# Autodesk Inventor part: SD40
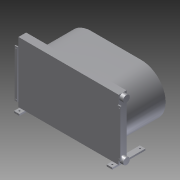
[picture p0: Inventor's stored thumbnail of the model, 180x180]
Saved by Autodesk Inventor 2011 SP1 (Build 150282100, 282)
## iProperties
Created: 2012-10
Part Number: SD40
Document SubType Name: Modeling
Designer: zazhorin
Density: 1 g/cm^3
Author: zazhorin
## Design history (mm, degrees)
sketch "Эскиз1"
  geometry: L1 (0, 0)-(50, 0); L2 (50, 0)-(50, 300); L3 (50, 300)-(0, 300); L4 (0, 300)-(0, 0); L5 (840, 0)-(890, 0); L6 (890, 0)-(890, 300); L7 (890, 300)-(840, 300); L8 (840, 300)-(840, 0); C1 r 7 at (25, 25); C2 r 7 at (25, 275); C3 r 7 at (865, 275); C4 r 7 at (865, 25)
  constraints: 16 end point, 4 centre point, 4 parallel, 2 horizontal, 2 perpendicular
  dimensions: "d0" = 50 distance of L1.start L1.end; "d1" = 300 distance of L3.end L1.start; "d2" = 790 distance between parallel lines of L8 L2; "d3" = 50 distance of L5.start L5.end; "d4" = 300 distance of L5.end L6.end; "d5" = 25 distance from line of C1.centre L1; "d6" = 14 diameter of C1; "d7" = 25 distance from line of C1.centre L4; "d8" = 25 distance from line of L3 C2.centre; "d9" = 14 diameter of C2; "d10" = 25 distance from line of C2.centre L4; "d11" = 300 distance between parallel lines of L5 L3; "d12" = 25 distance from line of C3.centre L8; "d13" = 25 distance from line of C3.centre L7; "d14" = 14 diameter of C3; "d15" = 25 distance from line of C4.centre L8; "d16" = 25 distance from line of C4.centre L5; "d17" = 14 diameter of C4
extrude "Выдавливание1" new body sketch "Эскиз1" distance "d18" = 15; taper "d19" = 0 deg
node "РабПлоскость1"
sketch "Эскиз3"
  geometry: L1 (445, 550)-(924, 550); L2 (445, 275)-(1052.827, 275); L3 (924, 275)-(924, 490); L4 (924, 490)-(899, 490); L5 (899, 490)-(899, 275); L6 (924, 275)-(924, 60); L7 (899, 60)-(899, 275); L8 (924, 60)-(899, 60); L9 (-34, 275)-(-34, 60); L10 (-9, 60)-(-9, 275); L11 (-34, 60)-(-9, 60); L12 (-34, 275)-(-34, 490); L13 (-9, 490)-(-9, 275); L14 (-34, 490)-(-9, 490); L15 (890, 0)-(0, 0); L16 (0, 0)-(50, 0) reference; L17 (445, 0)-(445, 767.594); C1 r 5 at (911.5, 474); C2 r 5 at (911.5, 76); C3 r 5 at (-21.5, 76); C4 r 5 at (-21.5, 474)
  constraints: 32 end point, 4 centre point, 4 perpendicular, 3 symmetric about line, 2 point on line, 1 collinear, 1 midpoint, 1 parallel, 1 other
  dimensions: "d23" = 215 distance of L3.start L3.end; "d24" = 25 distance of L3.end L4.end; "d25" = 199 distance from line of C1.centre L2; "d26" = 12.5 distance from line of C1.centre L5; "d27" = 10 diameter of C1; "d35" = 0 distance from line of L1.end L3; "d36" = 479 distance between parallel lines of L17 L3; "d38" = 12.5 distance from line of L12 C4.centre; "d39" = 12.5 distance from line of C3.centre L9; "d40" = 479 distance between parallel lines of L12 L17
extrude "Выдавливание2" join sketch "Эскиз3" distance "d28" = 10; taper "d29" = 0 deg
sketch "Эскиз4"
  geometry: L1 (890, -15)-(-9, -15); L2 (-9, -15)-(-9, -490); L3 (899, -490)-(899, -565); L4 (899, -565)-(-9, -565); L5 (-9, -565)-(-9, -490); L6 (890, -15)-(899, -15); L7 (899, -15)-(899, -490); 1 further point
  constraints: 14 end point, 2 horizontal, 2 perpendicular, 1 parallel
  dimensions: "d30" = 75 distance of L4.end L2.end; "d31" = 908 distance of L3.end L4.end
extrude "Выдавливание3" join sketch "Эскиз4" distance "d32" = 70; taper "d33" = 0 deg
sketch "Эскиз5"
  geometry: L1 (0, 0)-(0, 70) reference; L2 (0, 0)-(550, 0); L3 (75, 0)-(0, 0) reference; L4 (505, 0)-(75, 0) reference; L5 (275, 0)-(275, -74.016); C1 r 30 at (30, 35); C2 r 30 at (520, 35); 1 further point
  constraints: 4 end point, 2 centre point, 1 collinear, 1 perpendicular, 1 point on line, 1 symmetric about line, 1 other
  dimensions: "d42" = 60 diameter of C1; "d43" = 245 distance from line of C1.centre L5
extrude "Выдавливание4" join sketch "Эскиз5" distance "d44" = 35; taper "d45" = 0 deg
sketch "Эскиз6"
  geometry: L1 (-9, -565)-(899, -565) reference; L2 (445, -565)-(445, -485.449); L3 (672, -511)-(218, -511); L4 (672, -69)-(218, -69); A1 r 221 centre (672, -290) between (672, -511) and (672, -69); A2 r 221 centre (218, -290) between (218, -69) and (218, -511); 1 further point
  constraints: 6 end point, 4 point on circle, 2 centre point, 2 tangent, 1 midpoint, 1 parallel, 1 perpendicular, 1 symmetric about line, 1 other
  dimensions: "d46" = 442 diameter of A1
extrude "Выдавливание5" join sketch "Эскиз6" distance "d47" = 360; taper "d48" = 0 deg
node "Твердое тело1"
